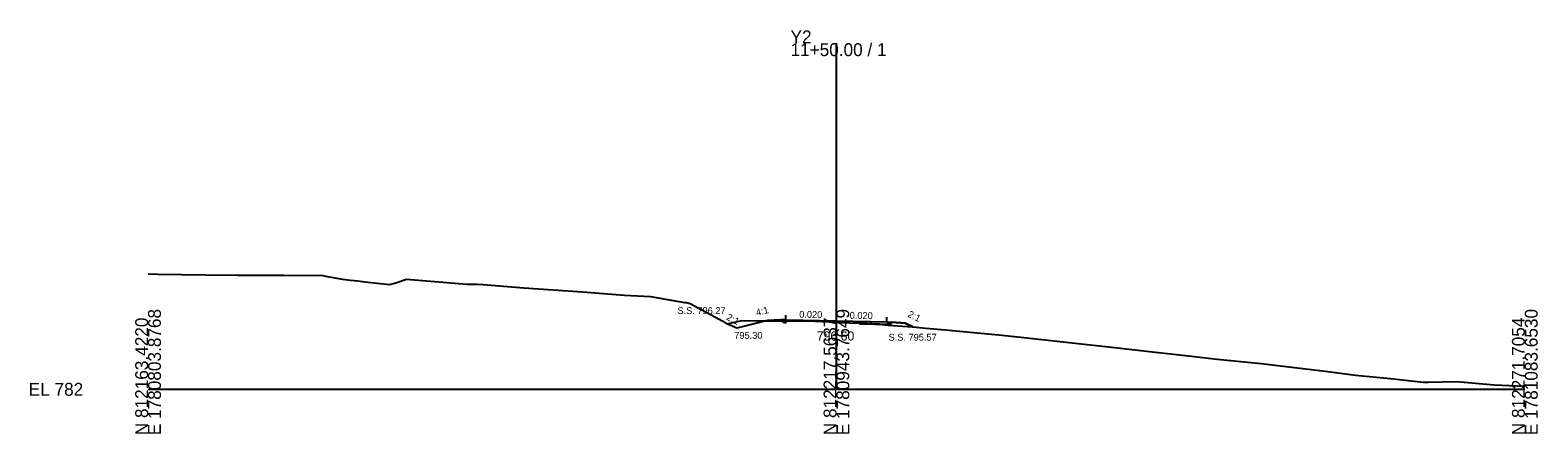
# Model space of a CAD drawing. Extents: x -26 to 303, y -10 to 3096.
# Drawn here: x -25.7 to 302.8, y 1990.3 to 2078.2 of the extents above; entities that cross this region are included whole.
import ezdxf

# ---------------------------------------------------------------- set-up
doc = ezdxf.new("R2010")
doc.units = 0
for name, color, linetype in [('Exist Cross Section Cell', 7, 'Continuous'), ('Exist XS Center Line Elevation Label', 7, 'Continuous'), ('Exist XS Ground Line', 7, 'Continuous'), ('Prop XS Ditch Slope Text', 7, 'Continuous'), ('Prop XS Ditch Standard Text', 7, 'Continuous'), ('Prop XS Dump Level', 7, 'Continuous'), ('Prop XS Earthwork Shape', 7, 'Continuous'), ('Prop XS EOT Tick Mark', 7, 'Continuous'), ('Prop XS Finish Grade', 7, 'Continuous'), ('Prop XS Finish Grade Earthwork', 7, 'Continuous'), ('Prop XS Finish Grade Pavement', 7, 'Continuous'), ('Prop XS Pvmt Edge Slope', 7, 'Continuous'), ('Prop XS SE Text', 7, 'Continuous'), ('Prop XS Side Slope Text', 7, 'Continuous'), ('Prop XS SS Elevation Text', 7, 'Continuous'), ('Prop XS Subgrade Earthwork', 7, 'Continuous')]:
    doc.layers.add(name, color=color, linetype=linetype)

msp = doc.modelspace()

# ---------------------------------------------------------------- linework, layer by layer
at = {"layer": 'Exist Cross Section Cell'}
for p, q in [((150, 2000), (150, 2075.32)), ((0, 2000), (150, 2000)), ((150, 2000), (300, 2000))]:
    msp.add_line(p, q, dxfattribs=at)
at = {"layer": 'Exist XS Ground Line'}
for p, q in [((0, 2025.11), (2.13, 2025.04)), ((2.13, 2025.04), (12.5, 2024.91)), ((12.5, 2024.91), (19.66, 2024.82)), ((19.66, 2024.82), (27.25, 2024.83)), ((27.25, 2024.83), (29.51, 2024.81)), ((29.51, 2024.81), (38.06, 2024.77)), ((38.06, 2024.77), (38.63, 2024.65)), ((38.63, 2024.65), (42.39, 2023.94)), ((42.39, 2023.94), (44.08, 2023.78)), ((44.08, 2023.78), (45.73, 2023.58)), ((53.96, 2023.16), (56.33, 2023.94)), ((56.33, 2023.94), (69.46, 2022.87)), ((45.73, 2023.58), (47.22, 2023.41)), ((47.22, 2023.41), (52.59, 2022.8)), ((52.59, 2022.8), (53.96, 2023.16)), ((69.46, 2022.87), (71.68, 2022.85)), ((71.68, 2022.85), (73, 2022.8)), ((73, 2022.8), (81.9, 2022.09)), ((81.9, 2022.09), (94.69, 2021.21)), ((94.69, 2021.21), (103.82, 2020.52)), ((103.82, 2020.52), (109.47, 2020.22)), ((109.47, 2020.22), (116.86, 2018.9)), ((116.86, 2018.9), (117.3, 2018.86)), ((117.3, 2018.86), (118.15, 2018.68)), ((118.15, 2018.68), (125.21, 2014.81)), ((125.21, 2014.81), (126.15, 2014.27)), ((126.15, 2014.27), (129.43, 2014.95)), ((129.43, 2014.95), (132.83, 2014.89)), ((132.83, 2014.89), (134.82, 2014.89)), ((134.82, 2014.89), (143.73, 2014.9)), ((143.73, 2014.9), (150, 2014.6)), ((150, 2014.6), (150.64, 2014.57)), ((150.64, 2014.57), (155.01, 2014.39)), ((155.01, 2014.39), (155.4, 2014.45)), ((155.4, 2014.45), (156.18, 2014.37)), ((156.18, 2014.37), (156.68, 2014.37)), ((156.68, 2014.37), (157.72, 2014.32)), ((157.72, 2014.32), (159.15, 2014.18)), ((159.15, 2014.18), (161.27, 2013.95)), ((161.27, 2013.95), (163.31, 2013.84)), ((163.31, 2013.84), (166.52, 2013.57)), ((166.52, 2013.57), (167.4, 2013.52)), ((167.4, 2013.52), (169.49, 2013.33)), ((169.49, 2013.33), (173.74, 2012.92)), ((173.74, 2012.92), (185.34, 2011.86)), ((185.34, 2011.86), (190.19, 2011.32)), ((190.19, 2011.32), (200.07, 2010.24)), ((200.07, 2010.24), (211.21, 2009.05)), ((211.21, 2009.05), (218.23, 2008.25)), ((218.23, 2008.25), (226.68, 2007.29)), ((226.68, 2007.29), (232.94, 2006.55)), ((232.94, 2006.55), (242.58, 2005.59)), ((242.58, 2005.59), (257.09, 2003.87)), ((257.09, 2003.87), (263.12, 2003.09)), ((263.12, 2003.09), (267.71, 2002.65)), ((267.71, 2002.65), (270.73, 2002.37)), ((270.73, 2002.37), (277.88, 2001.56)), ((277.88, 2001.56), (278.92, 2001.56)), ((278.92, 2001.56), (285.16, 2001.66)), ((285.16, 2001.66), (293.32, 2000.99)), ((293.32, 2000.99), (300, 2000.65))]:
    msp.add_line(p, q, dxfattribs=at)
at = {"layer": 'Prop XS Dump Level'}
for p, q in [((139, 2015.14), (150, 2014.92)), ((150, 2014.92), (161, 2014.7))]:
    msp.add_line(p, q, dxfattribs=at)
at = {"layer": 'Prop XS Earthwork Shape'}
for points in [[(134.64, 2014.89), (128.28, 2013.3), (126.15, 2014.27), (129.43, 2014.95), (132.83, 2014.89)], [(135, 2014.98), (134.64, 2014.89), (134.82, 2014.89), (138.1, 2014.89), (137.9, 2015.1)], [(138.43, 2014.57), (138.1, 2014.89), (139, 2014.9), (139, 2014.56)], [(155.01, 2014.24), (155.01, 2014.39), (155.4, 2014.45), (156.18, 2014.37), (156.68, 2014.37), (157.72, 2014.32), (159.15, 2014.18), (159.48, 2014.15)], [(159.48, 2014.15), (161.27, 2013.95), (163.31, 2013.84), (166.52, 2013.57), (166.63, 2013.57), (165, 2014.38), (162.1, 2014.61), (161.6, 2014.1)]]:
    msp.add_lwpolyline(points, close=True, dxfattribs=at)
at = {"layer": 'Prop XS EOT Tick Mark'}
for p, q in [((139, 2015.14), (139, 2016.14)), ((161, 2014.7), (161, 2015.7))]:
    msp.add_line(p, q, dxfattribs=at)
at = {"layer": 'Prop XS Finish Grade'}
for p, q in [((139, 2015.14), (137.9, 2015.1)), ((161, 2014.7), (162.1, 2014.61))]:
    msp.add_line(p, q, dxfattribs=at)
at = {"layer": 'Prop XS Finish Grade Earthwork'}
for p, q in [((128.28, 2013.3), (126.15, 2014.27)), ((135, 2014.98), (128.28, 2013.3)), ((137.9, 2015.1), (135, 2014.98)), ((162.1, 2014.61), (165, 2014.38)), ((165, 2014.38), (166.63, 2013.57))]:
    msp.add_line(p, q, dxfattribs=at)
at = {"layer": 'Prop XS Finish Grade Pavement'}
for p, q in [((139, 2015.14), (150, 2014.92)), ((150, 2014.92), (161, 2014.7))]:
    msp.add_line(p, q, dxfattribs=at)
at = {"layer": 'Prop XS Pvmt Edge Slope'}
for p, q in [((139, 2015.14), (138.43, 2014.57)), ((161, 2014.7), (161.6, 2014.1))]:
    msp.add_line(p, q, dxfattribs=at)
at = {"layer": 'Prop XS Subgrade Earthwork'}
for p, q in [((138.43, 2014.57), (137.9, 2015.1)), ((138.43, 2014.57), (139, 2014.56)), ((139, 2014.56), (139, 2014.9)), ((155.01, 2014.24), (155.01, 2014.39)), ((155.01, 2014.24), (161.6, 2014.1)), ((161.6, 2014.1), (162.1, 2014.61))]:
    msp.add_line(p, q, dxfattribs=at)

# ---------------------------------------------------------------- texts
at = {"layer": 'Exist Cross Section Cell'}
for s, p in [('Y2', (140, 2075.32)), ('11+50.00 / 1', (140, 2072.52)), ('EL 782', (-26, 1998.6))]:
    msp.add_text(s, height=2.8, dxfattribs=at).set_placement(p)
for s, p in [('E 1780803.8768', (2.8, 1990)), ('E 1780943.7649', (152.8, 1990)), ('E 1781083.6530', (302.8, 1990)), ('N 812163.4220', (0, 1990)), ('N 812217.5637', (150, 1990)), ('N 812271.7054', (300, 1990))]:
    msp.add_text(s, height=2.8, rotation=90, dxfattribs=at).set_placement(p)
at = {"layer": 'Exist XS Center Line Elevation Label'}
msp.add_text('796.60', height=2, dxfattribs=at).set_placement((145.71, 2010.6))
at = {"layer": 'Prop XS Ditch Slope Text'}
msp.add_text('4:1', height=1.5, rotation=14.0362, dxfattribs=at).set_placement((132.64, 2015.93))
at = {"layer": 'Prop XS Ditch Standard Text'}
msp.add_text('795.30', height=1.5, dxfattribs=at).set_placement((127.74, 2010.98))
at = {"layer": 'Prop XS Dump Level'}
for s, height, p in [('Eop', 0.3, (132.83, 2014.59)), ('Case1', 0.04, (135, 2014.94)), ('Eop', 0.3, (155.01, 2014.09)), ('Case1', 0.04, (165, 2014.34))]:
    msp.add_text(s, height=height, dxfattribs=at).set_placement(p)
at = {"layer": 'Prop XS SE Text'}
for p in [(141.88, 2015.58), (152.88, 2015.36)]:
    msp.add_text('0.020', height=1.5, rotation=358.8542, dxfattribs=at).set_placement(p)
at = {"layer": 'Prop XS Side Slope Text'}
for p in [(125.88, 2015.21), (165.4, 2015.86)]:
    msp.add_text('2:1', height=1.5, rotation=333.4349, dxfattribs=at).set_placement(p)
at = {"layer": 'Prop XS SS Elevation Text'}
for s, p in [('S.S. 796.27', (115.36, 2016.37)), ('S.S. 795.57', (161.36, 2010.57))]:
    msp.add_text(s, height=1.5, dxfattribs=at).set_placement(p)

doc.saveas('drawing.dxf')
